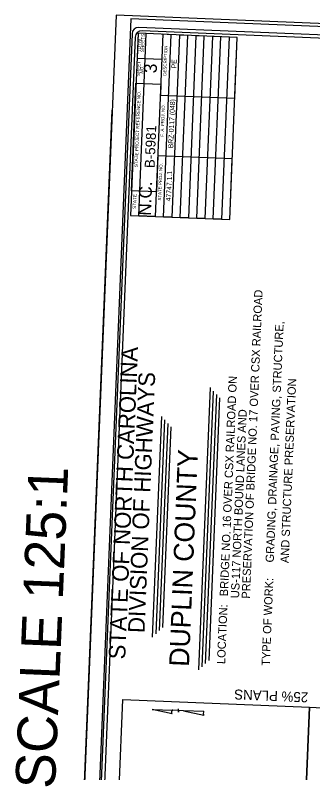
# Model space of a CAD drawing. Extents: x 2264506 to 2267635, y 507918 to 512596.
# Drawn here: x 2264506 to 2265629, y 509740 to 512596 of the extents above; entities that cross this region are included whole.
import ezdxf

# ---------------------------------------------------------------- set-up
doc = ezdxf.new("R2010")
doc.units = 0
for name, color, linetype in [('Default', 7, 'Continuous'), ('Matchline', 7, 'Continuous'), ('Prop Approach Slab', 7, 'Continuous'), ('Prop EOT Dash', 7, 'Continuous'), ('Prop Horizontal Alignment', 7, 'Continuous'), ('Prop Horizontal Alignment Station Label', 7, 'Continuous'), ('Prop Horizontal Alignment Tick Label', 7, 'Continuous'), ('Prop Horizontal Alignment Tick Large', 7, 'Continuous'), ('Prop Horizontal Alignment Tick Small', 7, 'Continuous')]:
    doc.layers.add(name, color=color, linetype=linetype)

msp = doc.modelspace()

# ---------------------------------------------------------------- linework, layer by layer
at = {"layer": 'Default'}
for points in [[(2265617.1, 509986.5), (2265575.7, 508983.7), (2264871.3, 509012.8), (2264912.8, 510015.6)], [(2265575.7, 508983.7), (2265617.1, 509986.5), (2265692.9, 509983.3), (2265651.5, 508980.6)]]:
    msp.add_lwpolyline(points, close=True, dxfattribs=at)
at = {"layer": 'Matchline'}
msp.add_line((2264698.7, 508031), (2264872.5, 512237.4), dxfattribs=at)
at = {"layer": 'Prop Approach Slab'}
for p, q in [((2265022.6, 509978.7), (2265022.6, 509978.7)), ((2265022.6, 509978.7), (2265022.6, 509978.7)), ((2265097.8, 509962.1), (2265022.6, 509978.7)), ((2265022.6, 509978.7), (2265100.7, 509975.5)), ((2265141.2, 509973.9), (2265098.4, 509975.6)), ((2265100.7, 509975.5), (2265098.5, 509975.6)), ((2265122, 509968.2), (2265122.6, 509981.2)), ((2265122.3, 509973.9), (2265122, 509968.1)), ((2265122, 509968.1), (2265122, 509968)), ((2265141.2, 509973.9), (2265217.8, 509957)), ((2265218.1, 509970.8), (2265141.2, 509973.9))]:
    msp.add_line(p, q, dxfattribs=at)
for centre, start_param, end_param in [((2265098.9, 509968.9), 0.216388, 2.908219), ((2265218.4, 509963.9), 0.201328, 3.141593)]:
    msp.add_ellipse(centre, major_axis=(0.33, 6.91), ratio=0.461098, start_param=start_param, end_param=end_param, dxfattribs=at)
at = {"layer": 'Prop Horizontal Alignment Station Label'}
for p, q in [((2265198.6, 510127.7), (2265242.6, 511191.8)), ((2265211.6, 510139.7), (2265254.5, 511178.8)), ((2265224.6, 510151.7), (2265266.5, 511165.8)), ((2265237.6, 510163.6), (2265278.5, 511152.8)), ((2265024.6, 510251.6), (2265058.9, 511082.8)), ((2265037.5, 510263.6), (2265070.9, 511069.8)), ((2265050.6, 510275.6), (2265082.8, 511056.8)), ((2265063.6, 510287.5), (2265094.8, 511043.8))]:
    msp.add_line(p, q, dxfattribs=at)
for points in [[(2265315.9, 511824.9), (2265344.2, 512511.9), (2265313, 512513.1), (2265284.6, 511826.2), (2265253.4, 511827.5), (2265281.8, 512514.4), (2265250.6, 512515.7), (2265222.2, 511828.8), (2265191, 511830.1), (2265219.3, 512517), (2265188.1, 512518.3), (2265159.7, 511831.4), (2265128.5, 511832.7), (2265156.9, 512519.6), (2265125.7, 512520.9), (2265097.3, 511834), (2265066.1, 511835.3), (2265094.5, 512522.2), (2265063.2, 512523.5), (2265034.8, 511836.5), (2264972.4, 511839.1), (2265000.8, 512526), (2264969.6, 512527.3), (2264941.2, 511840.4), (2265315.9, 511824.9), (2265325.3, 512053.9), (2265044.3, 512065.5), (2265038.7, 511930.2), (2264945, 511934.1), (2264961.8, 512340), (2265055.5, 512336.1), (2265053.8, 512294.4), (2265334.8, 512282.8), (2265344.2, 512511.9), (2264969.6, 512527.3), (2264965.7, 512433.7), (2265059.4, 512429.8)], [(2267545.8, 512443.4), (2264973, 512549.7)], [(2267070.7, 512450.5), (2264985, 512536.7)], [(2264947, 512525.8), (2264794.2, 508828.9)], [(2264959, 512512.8), (2264812.4, 508965.8)]]:
    msp.add_lwpolyline(points, dxfattribs=at)
for centre in [(2264971.8, 512524.7), (2264983.8, 512511.7)]:
    msp.add_arc(centre, 25, 87.6342, 177.6342, dxfattribs=at)
at = {"layer": 'Prop Horizontal Alignment Tick Label'}
msp.add_lwpolyline([(2267406.5, 508310.6), (2267578.5, 512473.3), (2264943, 512582.2), (2264771, 508419.5)], close=True, dxfattribs=at)
at = {"layer": 'Prop Horizontal Alignment Tick Large'}
msp.add_lwpolyline([(2264887.3, 512595.8), (2264713.6, 508389.4), (2267461.2, 508275.9), (2267635, 512482.3)], close=True, dxfattribs=at)
at = {"layer": 'Prop Horizontal Alignment Tick Small'}
for p, q in [((2265331.7, 510959.4), (2265331.7, 510959.4)), ((2265183.5, 510665.2), (2265183.5, 510665.2))]:
    msp.add_line(p, q, dxfattribs=at)

# ---------------------------------------------------------------- texts
at = {"layer": 'Default'}
msp.add_text('25% PLANS', height=37.5, rotation=177.6342, dxfattribs=at).set_placement((2265612.2, 510042.6))
at = {"layer": 'Prop EOT Dash'}
msp.add_text('SCALE 125:1', height=150, rotation=87.6342, dxfattribs=at).set_placement((2264656.1, 509677.7))
at = {"layer": 'Prop Horizontal Alignment'}
for s, height, p in [('PE', 18.75, (2265114.1, 512394.4)), ('BRZ-0117 (048)', 18.75, (2265101.9, 512093.4)), ('B-5981    ', 37.5, (2265031.9, 512018.7)), ('47747.1.1 ', 18.75, (2265093.6, 511893.4)), ('PRESERVATION OF BRIDGE NO. 17 OVER CSX RAILROAD', 31.25, (2265391.7, 510395.6)), ('GRADING, DRAINAGE, PAVING, STRUCTURE,   ', 31.25, (2265481.7, 510532)), ('BRIDGE NO. 16 OVER CSX RAILROAD ON      ', 31.25, (2265308.7, 510404.6)), ('AND STRUCTURE PRESERVATION              ', 31.25, (2265538, 510529.7)), ('US-117 NORTH BOUND LANES AND', 31.25, (2265350.7, 510397.2)), (' DUPLIN COUNTY  ', 75, (2265160.6, 510110.6))]:
    msp.add_text(s, height=height, rotation=87.6342, dxfattribs=at).set_placement(p)
at = {"layer": 'Prop Horizontal Alignment Station Label'}
for s, height, p in [('TOTAL', 12.5, (2264979.5, 512456)), ('SHEETS', 12.5, (2264992, 512456.3)), ('DESCRIPTION', 12, (2265076, 512367.4)), ('SHEET', 12.5, (2264976.7, 512365.5)), ('NO.', 12.5, (2264989.4, 512375.4)), ('3', 48.4, (2265040, 512376.4)), ('STATE PROJECT REFERENCE NO.', 12.499, (2264968.1, 512022.2)), ('F. A. PROJ. NO.', 12, (2265066.4, 512137.4)), ('STATE PROJ. NO.', 12, (2265056.5, 511896.8)), ('N.C.', 48.37, (2265017.8, 511839.1)), ('STATE', 12.5, (2264961.6, 511865.2)), ('STATE OF NORTH CAROLINA', 62.5, (2264921, 510166.2)), ('DIVISION OF HIGHWAYS', 62.5, (2264994, 510265.7)), ('TYPE OF WORK:', 31.25, (2265466.8, 510142.1)), ('LOCATION: ', 31.25, (2265298.2, 510149.1))]:
    msp.add_text(s, height=height, rotation=87.6342, dxfattribs=at).set_placement(p)

doc.saveas('drawing.dxf')
